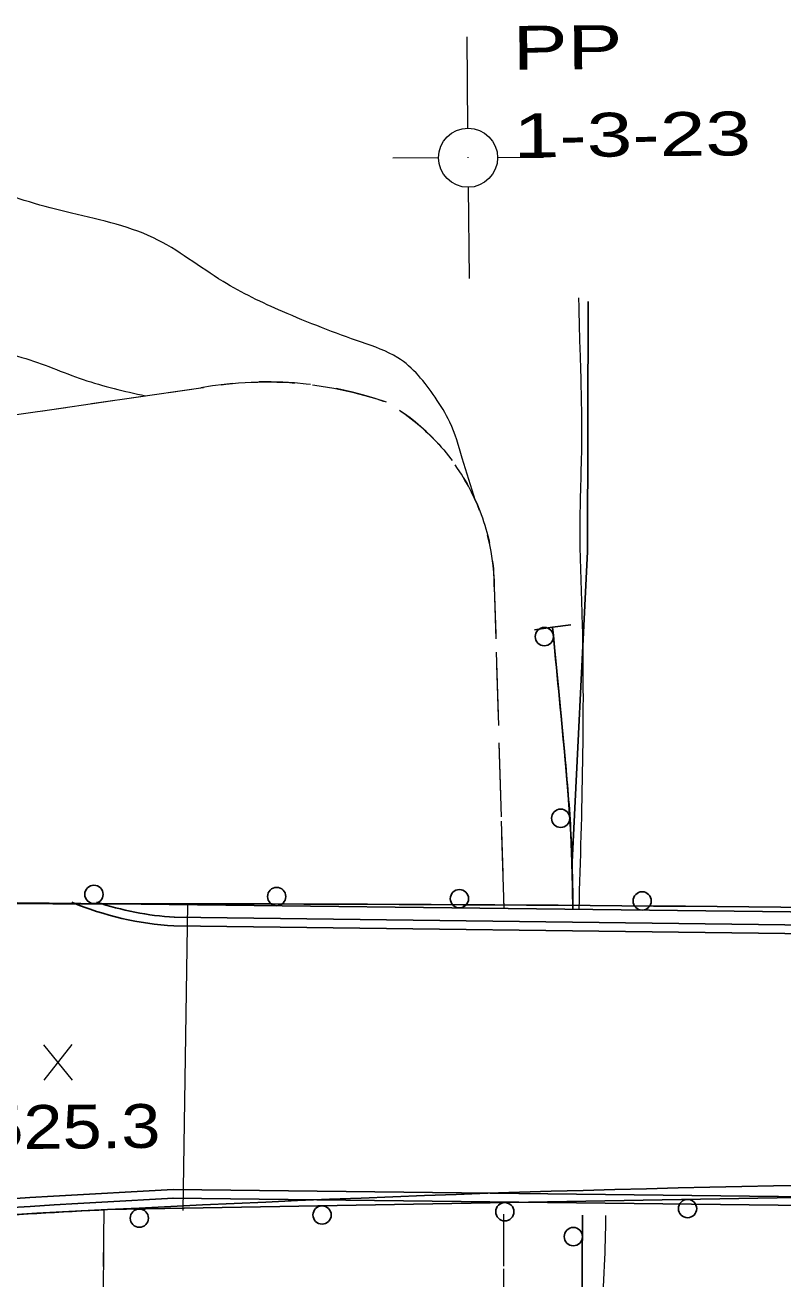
# Model space of a CAD drawing. Extents: x 2362213 to 2366494, y 6968794 to 6978110.
# Drawn here: x 2364354.4 to 2364437.3, y 6976463.5 to 6976600.8 of the extents above; entities that cross this region are included whole.
import ezdxf

# ---------------------------------------------------------------- set-up
doc = ezdxf.new("R2010")
doc.units = 0
doc.header["$LTSCALE"] = 1.9
doc.linetypes.add('MEDIUM_DASHED', pattern=[4.5, 3, -1.5])
for name, color, linetype, lineweight in [('1', 7, 'Continuous', 13), ('2', 7, 'Continuous', 25), ('31', 7, 'Continuous', 25), ('35', 7, 'Continuous', 13), ('4', 7, 'Continuous', 25), ('8', 7, 'Continuous', 13), ('9', 7, 'Continuous', 13)]:
    doc.layers.add(name, color=color, linetype=linetype, lineweight=lineweight)

msp = doc.modelspace()

# ---------------------------------------------------------------- linework, layer by layer
at = {"layer": '1'}
for p, q in [((2364402.859, 6976589.513), (2364402.784, 6976599.514)), ((2364399.65, 6976586.242), (2364394.651, 6976586.205)), ((2364402.89, 6976586.273), (2364402.89, 6976586.313)), ((2364406.13, 6976586.304), (2364411.13, 6976586.342)), ((2364402.921, 6976583.033), (2364402.996, 6976573.035))]:
    msp.add_line(p, q, dxfattribs=at)
msp.add_circle((2364402.89, 6976586.274), 3.24, dxfattribs=at)
at = {"layer": '2'}
for p, q in [((2364370.721, 6976503.124), (2364578.505, 6976500.512)), ((2364370.71, 6976502.163), (2364578.494, 6976499.551))]:
    msp.add_line(p, q, dxfattribs=at)
for points in [[(2364416.031, 6976570.519), (2364415.971, 6976543.156), (2364414.252, 6976508.429)], [(2364643.615, 6976469.31), (2364607.549, 6976469.827), (2364585.067, 6976469.883), (2364370.594, 6976472.35)], [(2364643.626, 6976470.27), (2364607.56, 6976470.787), (2364585.078, 6976470.843), (2364370.605, 6976473.311)]]:
    msp.add_lwpolyline(points, dxfattribs=at)
for centre, radius, start, end in [((2364372.815, 6976536.537), 34.438, 247.29822, 266.495), ((2364372.815, 6976536.537), 33.478, 251.55885, 266.495), ((2364516.087, 6973751.259), 2725.937, 93.05931, 94.82028), ((2364516.087, 6973751.259), 2724.977, 93.05931, 94.82028)]:
    msp.add_arc(centre, radius, start, end, dxfattribs=at)
at = {"layer": '31', "lineweight": 13}
for p, q in [((2364359.59, 6976485.297), (2364356.473, 6976489.147)), ((2364356.51, 6976485.268), (2364359.553, 6976489.176))]:
    msp.add_line(p, q, dxfattribs=at)
at = {"layer": '35'}
for points in [[(2364403.718, 6976548.69), (2364402.263, 6976553.387), (2364400.896, 6976557.323), (2364399.3, 6976560.038), (2364395.209, 6976564.369), (2364391.242, 6976566.061), (2364382.58, 6976569.44), (2364376.078, 6976572.718), (2364368.462, 6976577.496), (2364358.895, 6976580.334), (2364349.926, 6976583.279), (2364337.56, 6976589.111), (2364328.699, 6976590.257), (2364320.572, 6976590.961), (2364317.51, 6976591.031), (2364311.117, 6976590.409), (2364304.324, 6976590.695), (2364297.83, 6976589.963), (2364290.043, 6976586.459), (2364282.476, 6976581.996), (2364275.4, 6976577.15), (2364270.86, 6976572.946), (2364269.007, 6976570.159), (2364264.683, 6976565.336), (2364257.534, 6976557.878), (2364252.248, 6976554.228), (2364249.208, 6976553.119), (2364243.942, 6976552.809)], [(2364107.504, 6976572.841), (2364107.497, 6976571.431), (2364108.303, 6976569.738), (2364110.361, 6976567.937), (2364112.754, 6976566.56), (2364115.218, 6976565.043), (2364117.848, 6976564.018), (2364124.248, 6976561.019), (2364131.805, 6976557.07), (2364138.699, 6976553.587), (2364147.215, 6976550.948), (2364156.385, 6976549.885), (2364166.813, 6976549.154), (2364177.65, 6976548.368), (2364186.35, 6976548.41), (2364193.27, 6976548.516), (2364202.879, 6976548.548), (2364207.666, 6976548.923), (2364218.721, 6976549.669), (2364227.56, 6976549.643), (2364235.917, 6976548.072), (2364242.036, 6976548.131), (2364250.605, 6976549.252), (2364257.723, 6976553.82), (2364262.902, 6976559.139), (2364269.016, 6976562.887), (2364278.595, 6976564.229), (2364286.829, 6976561.727), (2364294.942, 6976564.464), (2364301.437, 6976565.156), (2364310.558, 6976565.103), (2364319.652, 6976564.63), (2364326.005, 6976565.42), (2364335.842, 6976565.834), (2364345.805, 6976565.549), (2364354.076, 6976564.397), (2364360.77, 6976561.991), (2364367.577, 6976560.196)], [(2364414.987, 6976570.929), (2364415.043, 6976568.228), (2364415.146, 6976564.719), (2364415.307, 6976555.151), (2364415.117, 6976545.678), (2364415.348, 6976536.18), (2364415.004, 6976504.026)], [(2364417.944, 6976470.481), (2364417.796, 6976464.99), (2364417.145, 6976452.483), (2364417.183, 6976439.014), (2364416.602, 6976418.136)]]:
    msp.add_spline(points, degree=3, dxfattribs=at)
at = {"layer": '4'}
for points in [[(2364410.153, 6976534.6), (2364412.14, 6976534.859), (2364414.128, 6976535.118)], [(2364414.374, 6976504.03), (2364414.285, 6976508.129), (2364414.146, 6976512.217), (2364413.855, 6976516.524), (2364413.474, 6976520.831), (2364412.837, 6976527.846), (2364412.14, 6976534.859)], [(2364092.443, 6976515.064), (2364097.717, 6976514.744), (2364102.999, 6976514.574), (2364110.069, 6976514.562), (2364117.129, 6976514.549), (2364138.763, 6976514.315), (2364160.396, 6976514.051), (2364185.901, 6976513.704), (2364211.396, 6976513.356), (2364230.978, 6976513.083), (2364250.562, 6976512.809), (2364265.206, 6976512.579), (2364279.839, 6976512.298), (2364285.152, 6976512.049), (2364290.437, 6976511.509), (2364300.371, 6976510.153), (2364310.295, 6976508.719), (2364319.668, 6976507.228), (2364329.083, 6976505.868), (2364346.534, 6976504.784), (2364364.015, 6976504.6), (2364475.265, 6976503.26)], [(2364754.359, 6976440.114), (2364747.687, 6976441.371), (2364741.014, 6976442.627), (2364723.282, 6976445.968), (2364705.549, 6976449.309), (2364682.388, 6976453.519), (2364659.198, 6976457.608), (2364637.622, 6976461.344), (2364616.026, 6976464.968), (2364600.764, 6976467.122), (2364585.401, 6976468.556), (2364474.392, 6976473.059), (2364363.444, 6976471.112), (2364355.708, 6976470.729), (2364347.983, 6976470.205), (2364340.737, 6976469.626), (2364333.494, 6976468.967), (2364325.821, 6976468.174), (2364318.148, 6976467.291)], [(2364415.032, 6976418.151), (2364415.287, 6976448.025), (2364415.423, 6976470.517)], [(2364415.032, 6976418.151), (2364415.287, 6976448.025), (2364415.423, 6976470.517)]]:
    msp.add_lwpolyline(points, dxfattribs=at)
for centre in [(2364411.236, 6976533.842), (2364413.028, 6976513.955), (2364361.948, 6976505.621), (2364381.948, 6976505.384), (2364401.946, 6976505.144), (2364421.945, 6976504.903), (2364366.92, 6976470.173), (2364386.917, 6976470.525), (2364406.914, 6976470.876), (2364426.911, 6976471.227), (2364414.409, 6976468.156)]:
    msp.add_circle(centre, 1, dxfattribs=at)
for points in [[(2364092.443, 6976515.064), (2364102.999, 6976514.574), (2364117.129, 6976514.549), (2364160.396, 6976514.051), (2364211.396, 6976513.356), (2364250.562, 6976512.809), (2364279.839, 6976512.298), (2364290.437, 6976511.509), (2364310.295, 6976508.719), (2364329.083, 6976505.868), (2364364.015, 6976504.6), (2364586.521, 6976502.088), (2364608.133, 6976501.974), (2364633.401, 6976503.435), (2364656.075, 6976506.231), (2364672.614, 6976507.339), (2364723.22, 6976507.061), (2364767.371, 6976506.161), (2364812.752, 6976506.263), (2364859.447, 6976508.028), (2364908.903, 6976512.939), (2364958.539, 6976520.891), (2364996.037, 6976528.69), (2365016.361, 6976533.563), (2365028.079, 6976537.045)], [(2364414.374, 6976504.03), (2364414.146, 6976512.217), (2364413.474, 6976520.831), (2364412.14, 6976534.859)], [(2364754.359, 6976440.114), (2364741.014, 6976442.627), (2364705.549, 6976449.309), (2364659.198, 6976457.608), (2364616.026, 6976464.968), (2364585.401, 6976468.556), (2364363.444, 6976471.112), (2364347.983, 6976470.205), (2364333.494, 6976468.967), (2364318.148, 6976467.291)]]:
    msp.add_spline(points, degree=3, dxfattribs=at)
at = {"layer": '8'}
for p, q in [((2364356.112, 6976558.536), (2364364.031, 6976559.682)), ((2364405.976, 6976532.121), (2364406.212, 6976524.122)), ((2364406.271, 6976522.122), (2364406.508, 6976514.124)), ((2364406.567, 6976512.125), (2364406.813, 6976504.128)), ((2364363.013, 6976464.878), (2364363.084, 6976471.089)), ((2364406.772, 6976470.615), (2364406.77, 6976466.615)), ((2364406.769, 6976464.615), (2364406.765, 6976456.614))]:
    msp.add_line(p, q, dxfattribs=at)
at = {"layer": '8', "linetype": 'MEDIUM_DASHED'}
for p, q in [((2364405.758, 6976539.288), (2364406.813, 6976504.118)), ((2364362.523, 6976418.871), (2364363.084, 6976471.089)), ((2364406.772, 6976470.615), (2364406.77, 6976418.263))]:
    msp.add_line(p, q, dxfattribs=at)
at = {"layer": '8'}
for points in [[(2364375.906, 6976561.415), (2364376.395, 6976561.48), (2364377.095, 6976561.546), (2364377.784, 6976561.613), (2364378.484, 6976561.66), (2364379.173, 6976561.696), (2364379.873, 6976561.713), (2364380.573, 6976561.73), (2364381.263, 6976561.726), (2364381.963, 6976561.713), (2364382.663, 6976561.689), (2364383.354, 6976561.646), (2364383.884, 6976561.601)], [(2364366.009, 6976559.971), (2364373.639, 6976561.073), (2364373.928, 6976561.126)], [(2364385.875, 6976561.4), (2364386.126, 6976561.372), (2364386.818, 6976561.269), (2364387.509, 6976561.166), (2364388.2, 6976561.042), (2364388.881, 6976560.909), (2364389.563, 6976560.755), (2364390.234, 6976560.601), (2364390.916, 6976560.428), (2364391.588, 6976560.254), (2364392.26, 6976560.051), (2364392.921, 6976559.857), (2364393.584, 6976559.633), (2364393.654, 6976559.604)], [(2364395.383, 6976558.62), (2364395.685, 6976558.413), (2364396.018, 6976558.176), (2364396.35, 6976557.93), (2364396.682, 6976557.683), (2364396.995, 6976557.426), (2364397.317, 6976557.169), (2364397.63, 6976556.902), (2364397.942, 6976556.626), (2364398.245, 6976556.349), (2364398.538, 6976556.071), (2364398.83, 6976555.784), (2364399.123, 6976555.497), (2364399.406, 6976555.2), (2364399.679, 6976554.892), (2364399.952, 6976554.585), (2364400.225, 6976554.277), (2364400.488, 6976553.96), (2364400.741, 6976553.642), (2364400.994, 6976553.315), (2364401.136, 6976553.116)], [(2364402.262, 6976551.467), (2364402.374, 6976551.278), (2364402.577, 6976550.92), (2364402.78, 6976550.572), (2364402.984, 6976550.213), (2364403.167, 6976549.845), (2364403.351, 6976549.477), (2364403.534, 6976549.109), (2364403.698, 6976548.73), (2364403.871, 6976548.362), (2364404.025, 6976547.983), (2364404.179, 6976547.605), (2364404.322, 6976547.216), (2364404.456, 6976546.827), (2364404.59, 6976546.438), (2364404.713, 6976546.049), (2364404.837, 6976545.65), (2364404.941, 6976545.261), (2364405.045, 6976544.862), (2364405.149, 6976544.463), (2364405.232, 6976544.074)], [(2364405.561, 6976542.107), (2364405.572, 6976542.037), (2364405.625, 6976541.637), (2364405.669, 6976541.228), (2364405.693, 6976540.818), (2364405.727, 6976540.408), (2364405.741, 6976539.998), (2364405.755, 6976539.588), (2364405.758, 6976539.288), (2364405.917, 6976534.12)]]:
    msp.add_lwpolyline(points, dxfattribs=at)
at = {"layer": '8', "linetype": 'MEDIUM_DASHED'}
msp.add_lwpolyline([(2364351.962, 6976505.036), (2364352.409, 6976527.371), (2364353.236, 6976558.119), (2364373.639, 6976561.073)], dxfattribs=at)
for centre, radius, start, end in [((2364380.828, 6976521.79), 39.936, 70.81024, 100.37027), ((2364382.25, 6976539.12), 23.508, 0.41071, 60.13929)]:
    msp.add_arc(centre, radius, start, end, dxfattribs=at)
at = {"layer": '9'}
msp.add_line((2364371.706, 6976471.021), (2364372.228, 6976504.508), dxfattribs=at)

# ---------------------------------------------------------------- texts
at = {"layer": '1', "width": 1.4}
for s, p in [('  PP', (2364402.819, 6976595.844)), ('  1-3-23', (2364402.911, 6976586.243))]:
    msp.add_text(s, height=4.8, rotation=0.546, dxfattribs=at).set_placement(p)
at = {"layer": '31', "width": 1.2}
msp.add_text('525.3', height=4.8, rotation=0.546, dxfattribs=at).set_placement((2364349.972, 6976477.704))

doc.saveas('drawing.dxf')
